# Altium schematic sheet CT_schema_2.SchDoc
size 229 x 185 mm
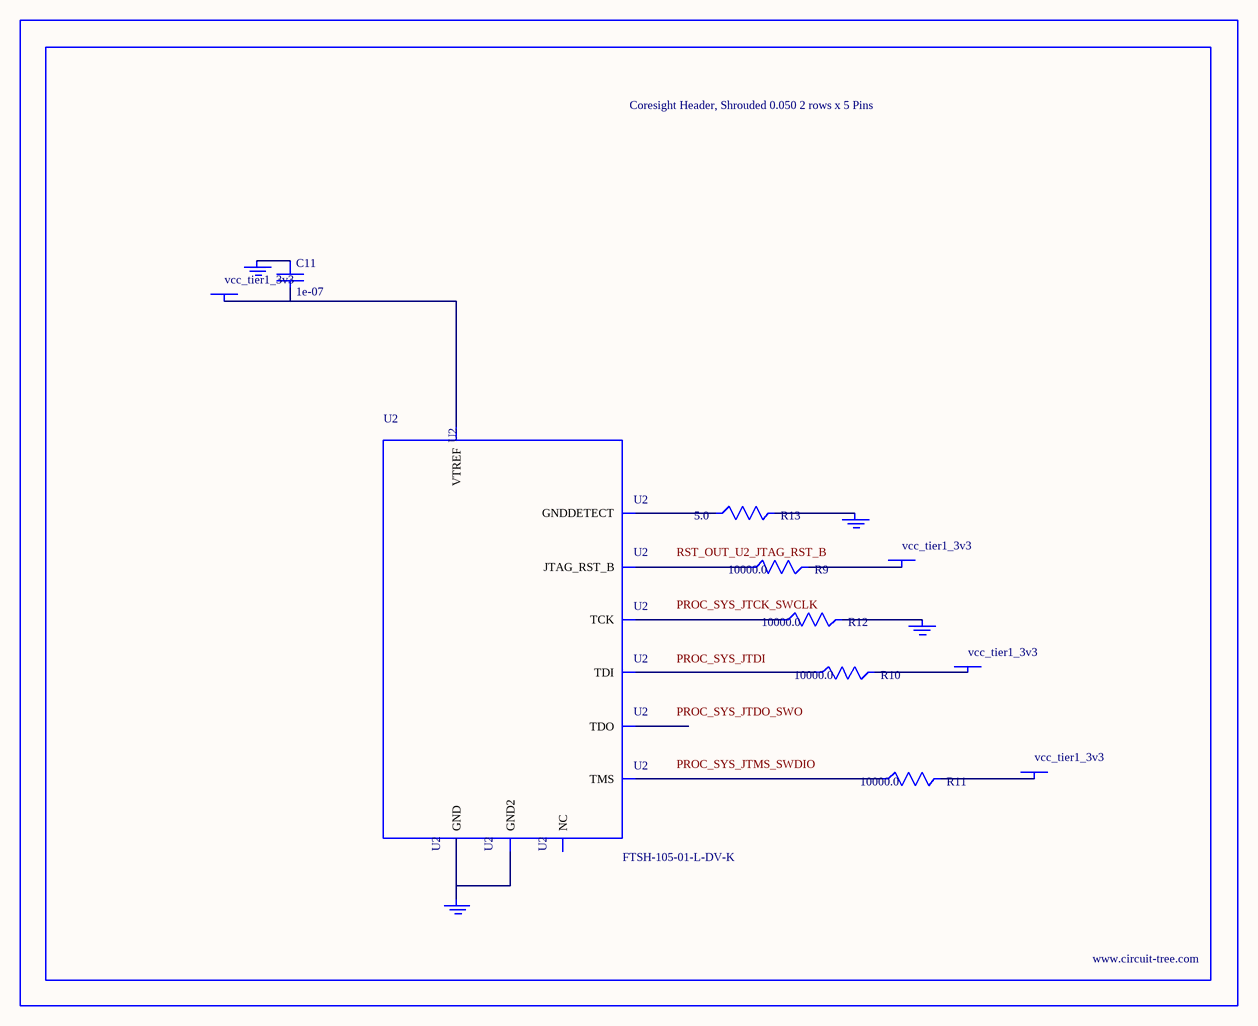
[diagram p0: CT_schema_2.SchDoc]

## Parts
BORDER1  (no value)
C11  1e-07  [C0402]
GND_INSTANCE_1_0  (no value)
GND_INSTANCE_1_1  (no value)
GND_INSTANCE_1_2  (no value)
GND_INSTANCE_1_3  (no value)
POWER_INSTANCE_1_0  vcc_tier1_3v3
POWER_INSTANCE_1_1  vcc_tier1_3v3
POWER_INSTANCE_1_2  vcc_tier1_3v3
POWER_INSTANCE_1_3  vcc_tier1_3v3
R9  10000.0  [R0603]
R10  10000.0  [R0603]
R11  10000.0  [R0603]
R12  10000.0  [R0603]
R13  5.0  [R0603]
U2  FTSH-105-01-L-DV-K  [SAMTEC_FTSH-105-01-L-DV-K]

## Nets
NetC11_1: C11.1 GND_INSTANCE_1_0.0(GND)
NetC11_2: C11.2 POWER_INSTANCE_1_0.0(PWR) U2.1(VTREF)
NetGND_INSTANCE_1_1_0: GND_INSTANCE_1_1.0(GND) R12.2
NetGND_INSTANCE_1_2_0: GND_INSTANCE_1_2.0(GND) R13.2
NetGND_INSTANCE_1_3_0: GND_INSTANCE_1_3.0(GND) U2.3(GND) U2.5(GND2)
NetPOWER_INSTANCE_1_1_0: POWER_INSTANCE_1_1.0(PWR) R11.2
NetPOWER_INSTANCE_1_2_0: POWER_INSTANCE_1_2.0(PWR) R10.2
NetPOWER_INSTANCE_1_3_0: POWER_INSTANCE_1_3.0(PWR) R9.2
NetR9_1: R9.1 U2.10(JTAG_RST_B)
NetR10_1: R10.1 U2.8(TDI)
NetR11_1: R11.1 U2.2(TMS)
NetR12_1: R12.1 U2.4(TCK)
NetR13_1: R13.1 U2.9(GNDDETECT)

Not connected (* = marked no-connect by the designer): U2 6(TDO) 7(NC)

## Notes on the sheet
- Labels drawn without touching a wire or pin: PROC_SYS_JTCK_SWCLK, PROC_SYS_JTDI, PROC_SYS_JTDO_SWO, PROC_SYS_JTMS_SWDIO, RST_OUT_U2_JTAG_RST_B

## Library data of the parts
BORDER1 = BORDER_PAGE1
C11 = C0402C104K3RACTU
GND_INSTANCE_1_0-GND_INSTANCE_1_3 = GND
POWER_INSTANCE_1_0-POWER_INSTANCE_1_3 = PWR
R9-R12 = RC0603JR-0710KL
R13 = ERJ-3GEYJ5R1V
